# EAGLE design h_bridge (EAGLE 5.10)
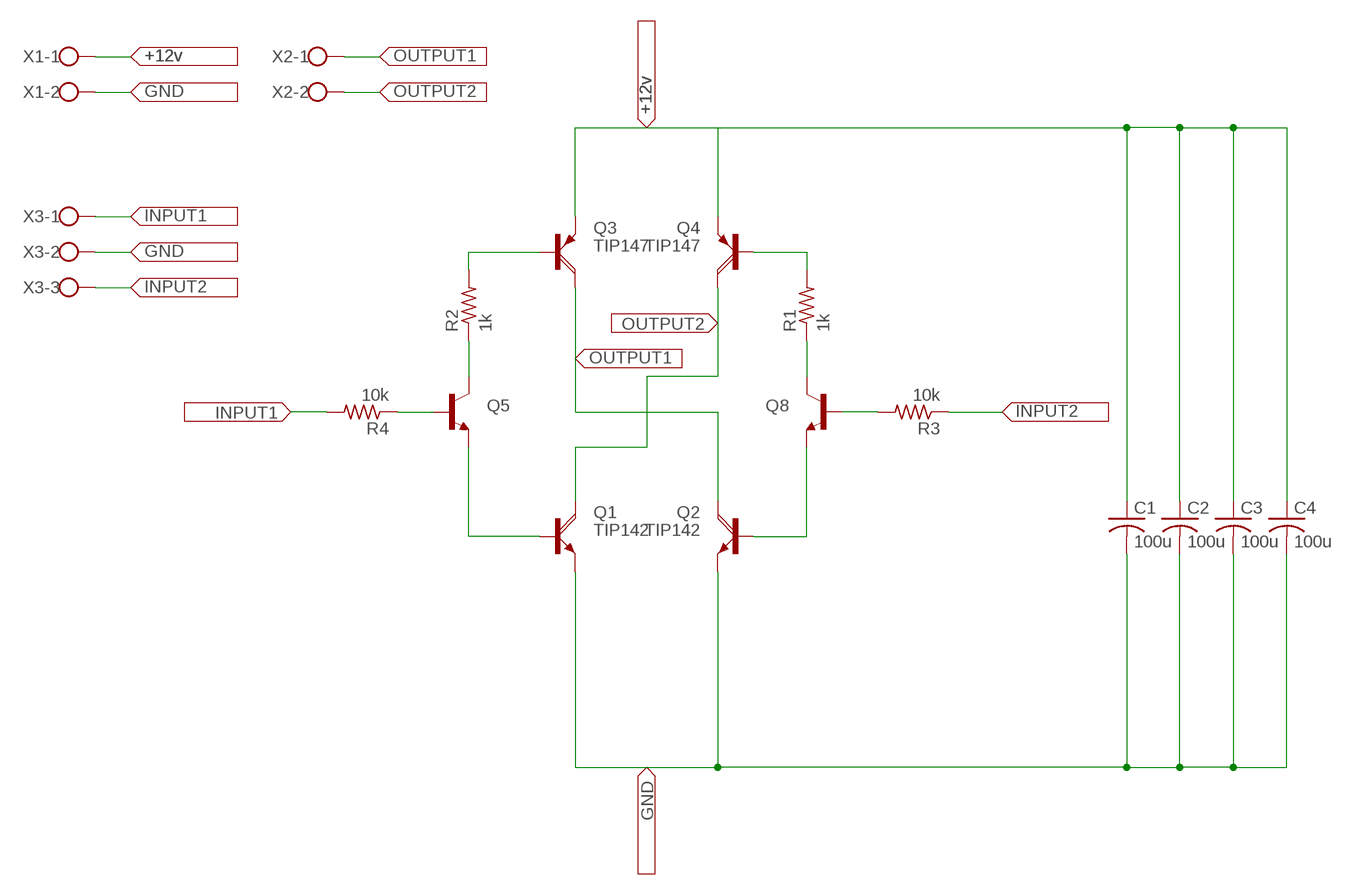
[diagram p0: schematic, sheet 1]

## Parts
C1  100u  C-US025-025X050  [C025-025X050]
C2  100u  C-US025-025X050  [C025-025X050]
C3  100u  C-US025-025X050  [C025-025X050]
C4  100u  C-US025-025X050  [C025-025X050]
Q1  TIP142  [SOT93]
Q2  TIP142  [SOT93]
Q3  TIP147  [SOT93]
Q4  TIP147  [SOT93]
Q5  TRANSISTOR_NPNTO92  [TO-92]
Q8  TRANSISTOR_NPNTO92  [TO-92]
R1  1k  R-US_0207/15  [0207/15]
R2  1k  R-US_0207/15  [0207/15]
R3  10k  R-US_0207/15  [0207/15]
R4  10k  R-US_0207/15  [0207/15]
X1  W237-02P  [W237-132]
X2  W237-02P  [W237-132]
X3  W237-03P  [W237-133]

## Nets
+12V: C1.1 C2.1 C3.1 C4.1 Q3.E Q4.E X1.1
GND: C1.2 C2.2 C3.2 C4.2 Q1.E Q2.E X1.2 X3.2
INPUT1: R4.2 X3.1
INPUT2: R3.1 X3.3
N$1: Q5.3(C) R2.1
N$2: Q3.B R2.2
N$3: Q4.B R1.2
N$4: Q8.3(C) R1.1
N$5: Q1.B Q5.1(E)
N$6: Q2.B Q8.1(E)
N$7: Q5.2(B) R4.1
N$8: Q8.2(B) R3.2
OUTPUT1: Q2.C Q3.C X2.1
OUTPUT2: Q1.C Q4.C X2.2

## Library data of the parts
C1-C4 = resistor:C-US: CAPACITOR, American symbol
Q1 Q2 = transistor-power:TIP142: NPN DARLINGTON TRANSISTOR
Q3 Q4 = transistor-power:TIP147: PNP DARLINGTON TRANSISTOR
Q5 Q8 = SparkFun:TRANSISTOR_NPN: Transistor NPN BJT configuration in SOT23 package. MMBT2222 is the common NPN we use. Double check BCE configuration again layout.
R1-R4 = resistor:R-US_: RESISTOR, American symbol
X1 X2 = con-wago-508:W237-02P: WAGO SREW CLAMP
X3 = con-wago-508:W237-03P: WAGO SREW CLAMP

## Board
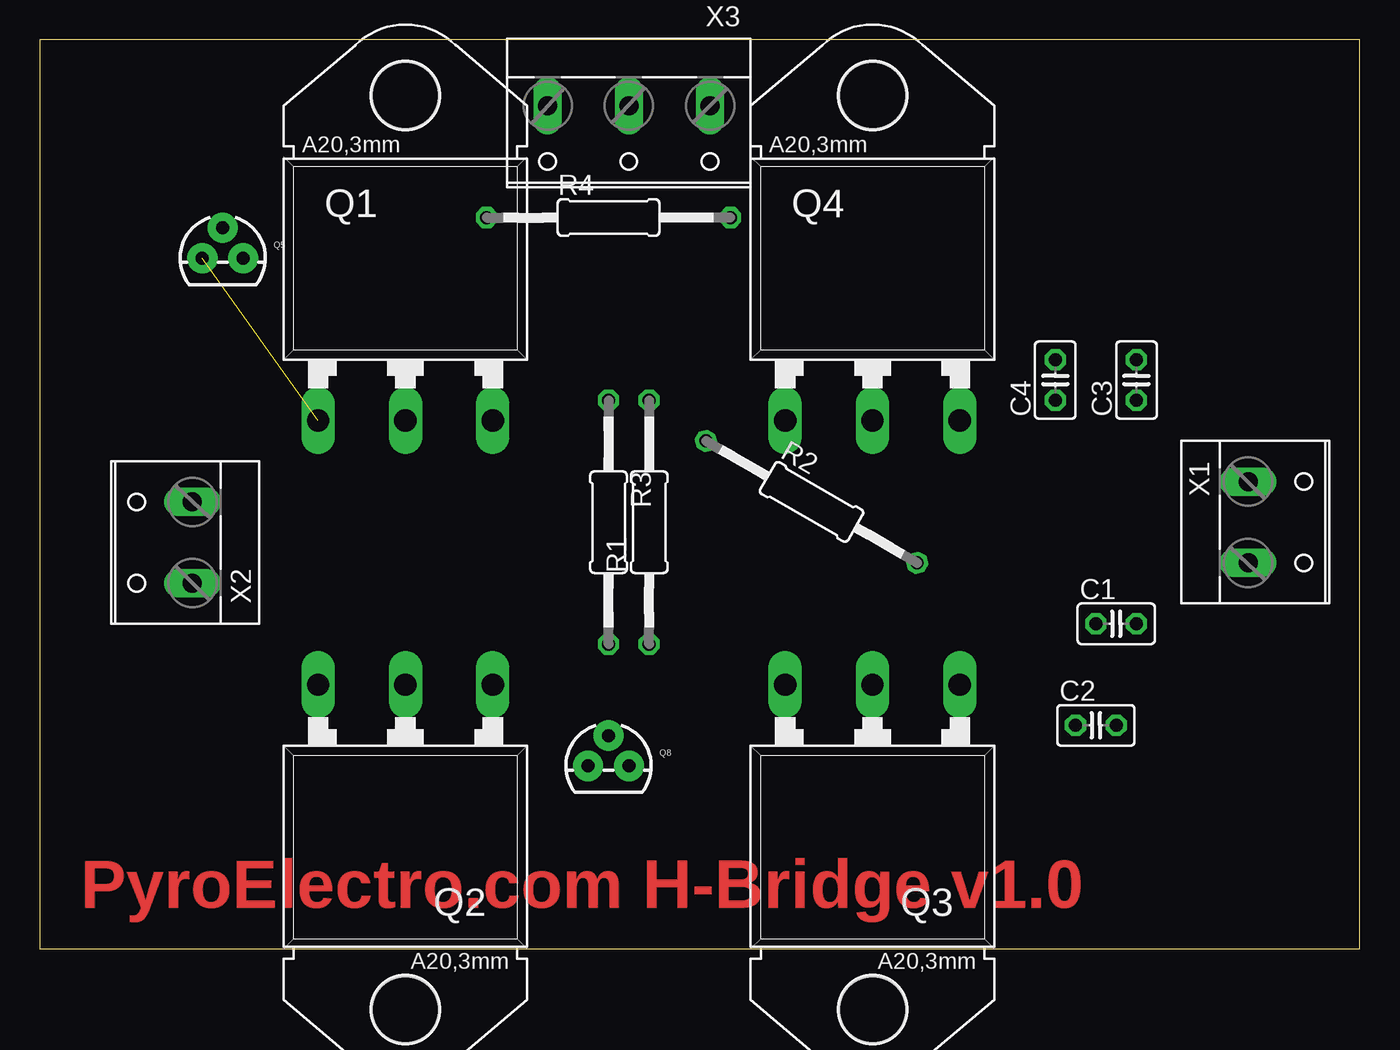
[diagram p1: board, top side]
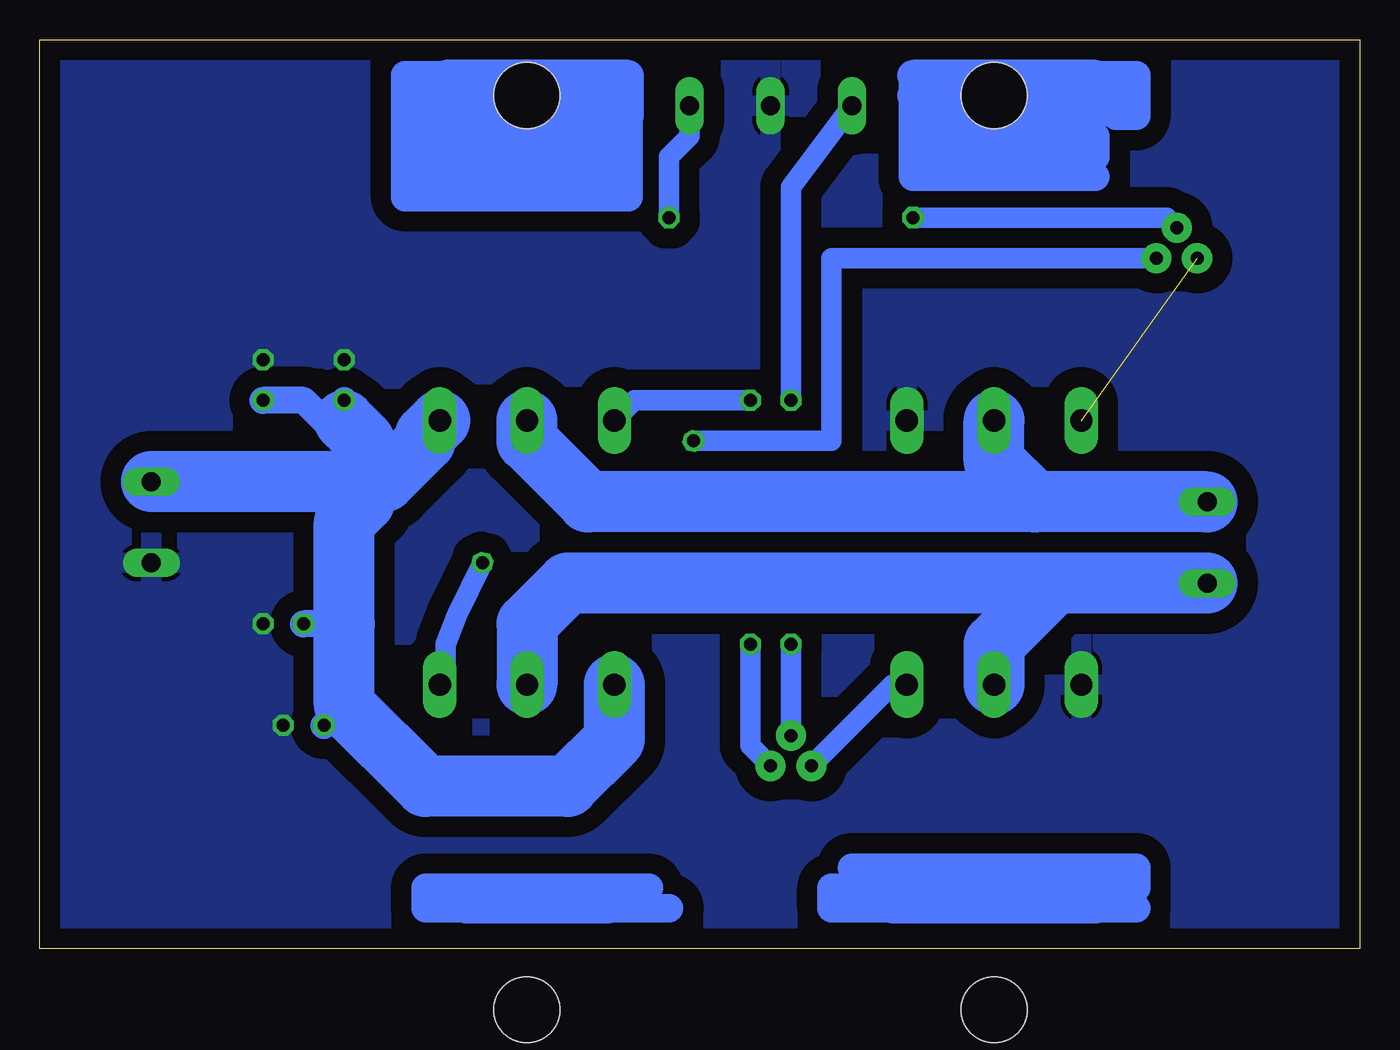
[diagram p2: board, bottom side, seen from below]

Size 82.53 x 56.82 mm. Coordinates in mm from the lower left corner, seen from the top.
Outline: 0,0 82.53,0 82.53,56.82 0,56.82 0,0
Copper layers (1*16): Top 0.035mm / dielectric 1.5mm / Bottom 0.035mm
Design rules "default": minimum track width 10mil, minimum drill 24mil, track to track 8mil, track to pad 8mil, pad to pad 8mil, via to via 8mil, smd to smd 8mil, copper to edge 40mil, drill to drill 8mil, minimum pad ring 10mil, minimum via ring 8mil, stop-mask expansion 4mil, vias tented up to drill 0mil, thermal gap 10mil

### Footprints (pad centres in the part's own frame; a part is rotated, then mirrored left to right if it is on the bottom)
C025-025X050 = drill 0.813 octagon: 1 -1.27,0; 2 1.27,0
SOT93 = drill 1.397 long: B -5.461,-10.16; C 0,-10.16; E 5.461,-10.16 | hole 4.115: 0,10.16
TO-92 = drill 0.813 pad 1.88 round: 1 -1.27,0; 2 0,1.905; 3 1.27,0
0207/15 = drill 0.813 octagon: 1 -7.62,0; 2 7.62,0
W237-132 = drill 1.194 long: 1 -2.54,-0.635; 2 2.54,-0.635
W237-133 = drill 1.194 long: 1 -5.08,-0.635; 2 0,-0.635; 3 5.08,-0.635

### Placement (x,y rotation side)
C1  67.31,20.32 0 top
C2  66.04,13.97 0 top
C3  68.58,35.56 90 top
C4  63.5,35.56 90 top
Q1  22.86,43.18 0 top
Q2  22.86,6.35 180 top
Q3  52.07,6.35 180 top
Q4  52.07,43.18 0 top
Q5  11.43,43.18 0 top
Q8  35.56,11.43 0 top
R1  38.1,26.67 90 top
R2  48.26,27.94 330 top
R3  35.56,26.67 270 top
R4  35.56,45.72 0 top
X1  76.2,26.67 270 top
X2  8.89,25.4 90 top
X3  36.83,52.07 180 top

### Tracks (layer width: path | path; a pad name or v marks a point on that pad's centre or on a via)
+12V
  Bottom 1.676: 63.5,20.32 C1.1 | 63.5,15.24 C2.1 | 63.5,31.75 C4.1 | 62.87,32.38 63.5,31.75 | C3.1 66.04,34.29 63.5,31.75 | 62.23,27.94 60.96,29.21
  Bottom 3.81: X1.1 60.96,29.21 58.42,31.75 58.42,32.13 Q4.E | Q3.E 46.61,13.08 49.53,10.16 58.42,10.16 63.5,15.24 63.5,20.32 63.5,26.67 62.23,27.94 62.23,31.75 62.87,32.38 63.5,33.02
GND
  pour Bottom (isolate 1.27): 0,57.15 82.55,55.88 82.55,0 0,0
INPUT1
  Bottom 1.27: R4.2 43.18,49.53 41.91,50.8 X3.1
INPUT2
  Bottom 1.27: R3.1 35.56,47.62 X3.3
N$1
  Bottom 1.27: R2.1 33.02,31.75 33.02,43.18 Q5.3
N$2
  Bottom 1.27: R2.2 56.45,20.89 57.15,19.05 57.15,16.89 Q3.B
N$3
  Bottom 1.27: R1.2 45.34,34.29 Q4.B
N$4
  Bottom 1.27: Q8.3 38.1,12.7 R1.1
N$5  (1 unrouted)
N$6
  Bottom 1.27: Q2.B 29.21,16.51 Q8.1
N$7
  Bottom 1.27: R4.1 12.06,45.72 Q5.2
N$8
  Bottom 1.27: Q8.2 R3.2
N$9
  Bottom 1.778: 13.97,2.54 33.02,2.54 33.02,3.81 13.97,3.81 13.97,5.08 31.75,5.08
N$10
  Bottom 1.93: 16.51,2.54 29.21,2.54 29.21,3.81 17.78,3.81
N$12
  Bottom 1.93: 46.99,2.54 55.88,2.54
N$14
  Bottom 1.778: 45.72,54.61 45.72,46.99 59.69,46.99 59.69,54.61 46.99,54.61 46.99,48.26 58.42,48.26 58.42,53.34 48.26,53.34 48.26,49.53 57.15,49.53 57.15,52.07 53.34,52.07 53.34,50.8 55.88,50.8
  Bottom 1.93: 57.15,54.61 45.72,54.61 45.72,52.07 55.88,52.07 55.88,53.34 48.26,53.34 48.26,50.8 52.07,50.8
N$15
  Bottom 1.778: 16.51,48.26 27.94,48.26 27.94,54.61 13.97,54.61 13.97,52.07 15.24,52.07 15.24,53.34 16.51,53.34 16.51,52.07 26.67,52.07 26.67,49.53 16.51,49.53 16.51,50.8 25.4,50.8
  Bottom 1.93: 27.94,54.61 16.51,54.61 16.51,53.34 26.67,53.34 | 26.67,53.34 27.94,53.34 | 26.67,53.34 26.67,52.07 19.05,52.07 19.05,50.8 22.86,50.8
N$16
  Bottom 1.778: 43.18,2.54 58.42,2.54 58.42,3.81 44.45,3.81
OUTPUT1
  Bottom 3.81: X2.1 19.05,22.86 | 19.05,22.86 49.53,22.86 52.07,20.32 Q3.C | Q2.C 22.86,19.05 19.05,22.86
OUTPUT2
  Bottom 3.81: X2.2 20.32,27.94 | 20.32,27.94 22.86,30.48 Q1.C | Q4.C 52.07,31.75 48.26,27.94 20.32,27.94

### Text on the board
Top: PyroElectro.com H-Bridge v1.0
